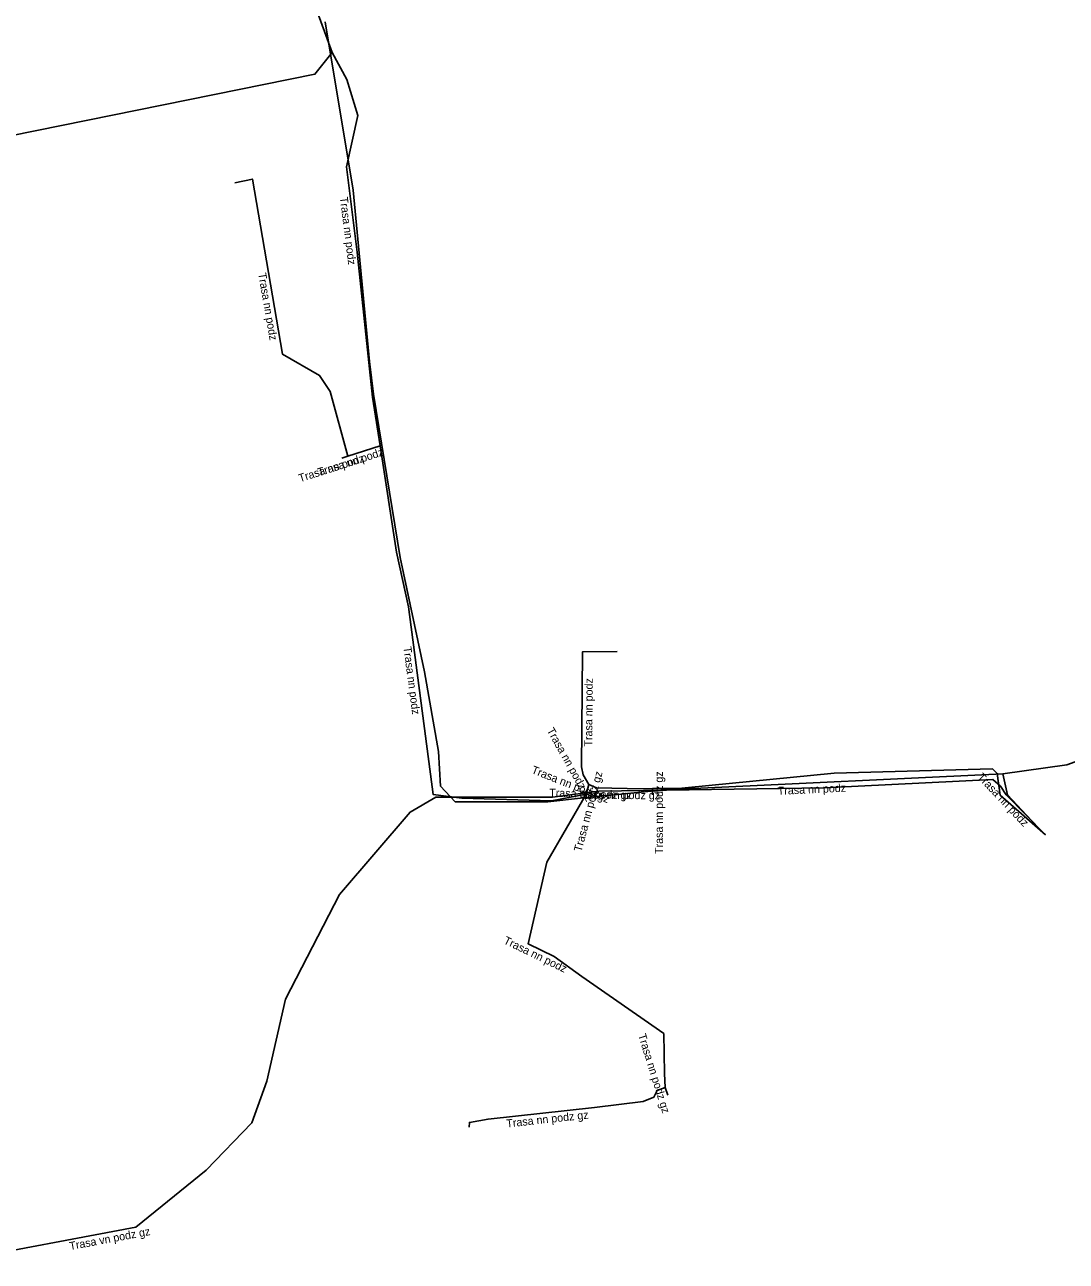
# Model space of a CAD drawing. Extents: x -677644 to -676951, y -1057278 to -1056718.
# Drawn here: x -677109.5 to -677044.4, y -1057108.6 to -1057031.3 of the extents above; entities that cross this region are included whole.
import ezdxf

# ---------------------------------------------------------------- set-up
doc = ezdxf.new("R2010")
doc.units = 0
for name, color, linetype in [('Popiskový text - Ostatní atributy Trasy', 7, 'Continuous'), ('Spojnice NN', 7, 'Continuous'), ('Spojnice VN', 7, 'Continuous')]:
    doc.layers.add(name, color=color, linetype=linetype)

msp = doc.modelspace()

# ---------------------------------------------------------------- linework, layer by layer
at = {"layer": 'Spojnice NN'}
for points in [[(-677096.31, -1057013.84), (-677094.45, -1057016.32), (-677093.97, -1057017.89), (-677093.54, -1057020.54), (-677092.11, -1057028.05), (-677090.99, -1057031.08), (-677090.29, -1057033.02)], [(-677143.594, -1057041.946), (-677140.301, -1057041.057), (-677128.017, -1057041.737), (-677117.92, -1057039.54), (-677115.14, -1057039.2), (-677091.36, -1057034.39), (-677090.29, -1057033.02)], [(-677090.29, -1057033.02), (-677089.36, -1057034.71), (-677088.67, -1057036.97), (-677089.39, -1057040.17), (-677088.72, -1057045.51), (-677087.76, -1057054.56), (-677087.293, -1057057.592)], [(-677096.361, -1057041.174), (-677095.272, -1057040.933), (-677093.378, -1057051.878), (-677091.066, -1057053.203), (-677090.402, -1057054.207), (-677089.306, -1057058.244)], [(-677089.306, -1057058.244), (-677089.681, -1057058.364)], [(-677089.306, -1057058.244), (-677087.293, -1057057.592)], [(-677087.293, -1057057.592), (-677086.27, -1057064.24), (-677085.51, -1057067.67), (-677083.96, -1057079.39), (-677082.17, -1057079.62), (-677076.57, -1057079.78), (-677074.41, -1057079.37)], [(-677072.47, -1057070.46), (-677074.63, -1057070.47), (-677074.69, -1057077.65), (-677074.59, -1057078.16)], [(-677029.27, -1057077.87), (-677033.28, -1057078.91), (-677035.21, -1057074.87), (-677037.02, -1057075.31), (-677041.08, -1057076.34), (-677044.37, -1057077.54), (-677048.36, -1057078.09)], [(-677074.59, -1057078.16), (-677074.25, -1057078.77)], [(-677070.26, -1057079.02), (-677067.67, -1057079.01), (-677048.36, -1057078.09)], [(-677045.688, -1057081.9), (-677045.962, -1057081.656), (-677048.08, -1057079.41), (-677048.36, -1057078.09)], [(-677074.25, -1057078.77), (-677074.41, -1057079.37)], [(-677074.25, -1057078.77), (-677073.77, -1057078.96)], [(-677073.77, -1057078.96), (-677071.85, -1057079.02)], [(-677071.85, -1057079.02), (-677070.85, -1057079.03), (-677070.26, -1057079.02)], [(-677070.26, -1057079.4), (-677070.26, -1057079.02)], [(-677074.41, -1057079.37), (-677076.86, -1057083.61), (-677078.04, -1057088.71), (-677076.41, -1057089.5), (-677074.68, -1057090.75), (-677069.56, -1057094.32), (-677069.52, -1057096.81), (-677069.46, -1057097.7)], [(-677069.46, -1057097.7), (-677069.96, -1057097.87), (-677070.17, -1057098.29), (-677070.84, -1057098.57), (-677073.89, -1057098.94), (-677080.54, -1057099.67), (-677081.7, -1057099.87), (-677081.71, -1057100.18)], [(-677069.46, -1057097.7), (-677069.31, -1057098.18)]]:
    msp.add_lwpolyline(points, dxfattribs=at)
at = {"layer": 'Spojnice VN'}
for points in [[(-677045.688, -1057081.9), (-677048.52, -1057079.43), (-677048.71, -1057078.07), (-677049, -1057077.79), (-677058.91, -1057078.06), (-677074.58, -1057079.6), (-677076.8, -1057079.84), (-677082.6, -1057079.84), (-677083.51, -1057078.86), (-677083.63, -1057076.7), (-677084.51, -1057071.73), (-677086.04, -1057064.58), (-677087.71, -1057054.38), (-677087.95, -1057052.34), (-677088.98, -1057041.63), (-677090.73, -1057031.12)], [(-677113.84, -1057108.55), (-677102.55, -1057106.42), (-677098.16, -1057102.85), (-677095.31, -1057099.9), (-677094.36, -1057097.29), (-677093.21, -1057092.18), (-677089.82, -1057085.64), (-677085.41, -1057080.49), (-677083.8, -1057079.55), (-677076.52, -1057079.55), (-677073.62, -1057079.17), (-677059.51, -1057078.98), (-677048.99, -1057078.45), (-677048.5, -1057078.87), (-677048.15, -1057079.4), (-677045.688, -1057081.9)]]:
    msp.add_lwpolyline(points, dxfattribs=at)

# ---------------------------------------------------------------- texts
at = {"layer": 'Popiskový text - Ostatní atributy Trasy'}
for s, rotation, p in [('Trasa nn podz', 277.15143, (-677089.806, -1057042.078)), ('Trasa nn podz', 279.81764, (-677094.911, -1057046.832)), ('Trasa nn podz', 17.74467, (-677092.294, -1057059.882)), ('Trasa nn podz', 17.94686, (-677091.093, -1057059.507)), ('Trasa nn podz', 277.53379, (-677085.834, -1057070.18)), ('Trasa nn podz', 89.52122, (-677074.029, -1057076.393)), ('Trasa nn podz gz', 299.13429, (-677076.883, -1057075.381)), ('Trasa nn podz gz', 338.40469, (-677077.869, -1057078.036)), ('Trasa nn podz gz', 75.06858, (-677074.706, -1057083)), ('Trasa nn podz gz', 90, (-677069.61, -1057083.104)), ('Trasa nn podz', 313.32351, (-677049.991, -1057078.332)), ('Trasa nn podz gz', 358.21009, (-677076.722, -1057079.518)), ('Trasa nn podz gz', 359.42706, (-677074.955, -1057079.639)), ('Trasa nn podz', 2.72772, (-677062.422, -1057079.411)), ('Trasa nn podz', 334.14227, (-677079.61, -1057088.672)), ('Trasa nn podz gz', 287.35402, (-677071.167, -1057094.417)), ('Trasa nn podz gz', 6.26453, (-677079.37, -1057100.195)), ('Trasa vn podz gz', 10.68399, (-677106.66, -1057107.857))]:
    msp.add_text(s, height=0.5, rotation=rotation, dxfattribs=at).set_placement(p)

doc.saveas('drawing.dxf')
